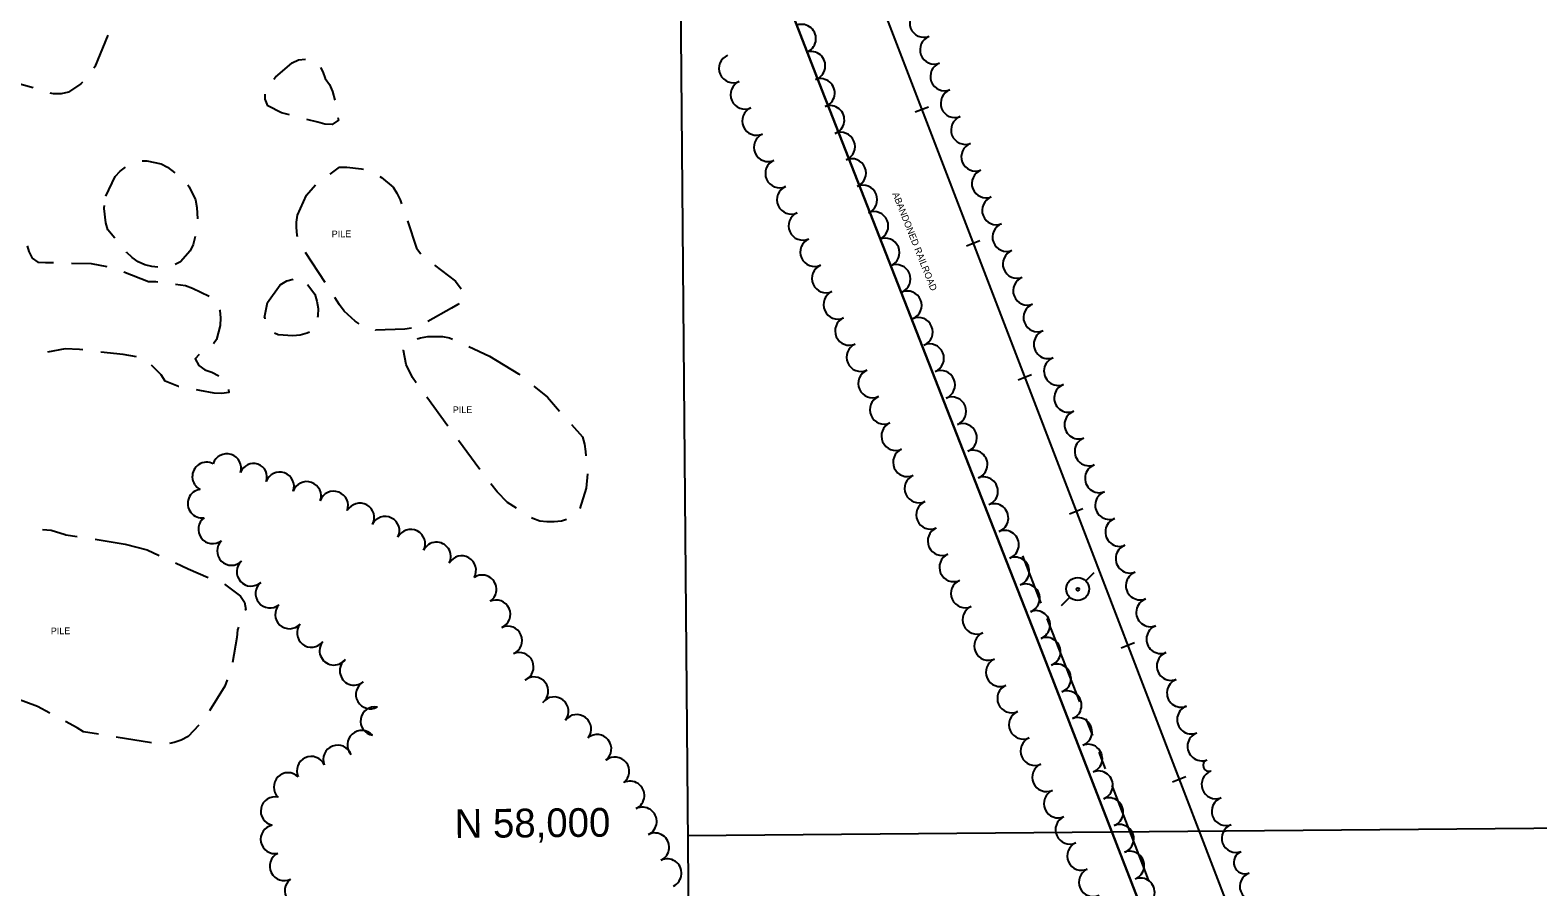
# Model space of a CAD drawing. Extents: x -2233 to 187241, y 4582 to 150524.
# Drawn here: x 104550 to 105601, y 57965 to 58561 of the extents above; entities that cross this region are included whole.
import ezdxf

# ---------------------------------------------------------------- set-up
doc = ezdxf.new("R2010")
doc.units = 0
for name, color, linetype in [('BLDG', 7, 'Continuous'), ('DIVISIONS', 7, 'Continuous'), ('DV_X_Corp_Line', 7, 'Continuous'), ('GRID', 7, 'Continuous'), ('RR', 7, 'Continuous'), ('TI_BORDER', 7, 'Continuous'), ('TRANSPWRLN', 7, 'Continuous'), ('TREES', 7, 'Continuous')]:
    doc.layers.add(name, color=color, linetype=linetype)

msp = doc.modelspace()

# ---------------------------------------------------------------- linework, layer by layer
at = {"layer": 'BLDG'}
for p, q in [((104720.3, 58527.3), (104721.4, 58528.6)), ((104756, 58385.6), (104742.3, 58406.5)), ((104856.1, 58341), (104870.5, 58334.3)), ((104841.6, 58285.6), (104826.8, 58305.8)), ((104863.7, 58255.3), (104849, 58275.5)), ((104595.6, 58206.7), (104616.6, 58203.3)), ((104635, 58064.9), (104610.3, 58068.9))]:
    msp.add_line(p, q, dxfattribs=at)
for points in [[(104604.6, 58558), (104595.4, 58536), (104594.7, 58535)], [(104721.4, 58528.6), (104732.9, 58538.6), (104737.5, 58540.7), (104742.2, 58541.2)], [(104752.7, 58535.4), (104754.3, 58532.4), (104756.1, 58527.7), (104759, 58523.5), (104761.1, 58518.8), (104762.8, 58512.7)], [(104552.4, 58521.2), (104536.5, 58525.8), (104531.2, 58525.4), (104528.1, 58525.1)], [(104586.9, 58525.3), (104585.6, 58524), (104577.1, 58518.3), (104572, 58517.1), (104566.6, 58517.1), (104564.4, 58517.6)], [(104731.2, 58502.4), (104725.5, 58503.8), (104716.1, 58508.7), (104714.2, 58513.3), (104714.1, 58516.9)], [(104764.9, 58500.5), (104765.2, 58498.7), (104761, 58495.8), (104755.8, 58496), (104750.9, 58497.3), (104743.3, 58499.3)], [(104628.4, 58470.5), (104631.8, 58470.5), (104641.7, 58468.4), (104646.2, 58465.9), (104651.2, 58462)], [(104603.1, 58445.8), (104609.7, 58459.4), (104613.2, 58463.1), (104616.9, 58466.1)], [(104759.4, 58461.2), (104766.1, 58466.1), (104771.2, 58465.9), (104781.4, 58464.9), (104782.7, 58464.5)], [(104794.1, 58459.6), (104795.3, 58458.9), (104803.3, 58452.1), (104806, 58447.9), (104808.3, 58443.3), (104809.3, 58440.5)], [(104660.3, 58453.6), (104661.3, 58452.3), (104665.6, 58443.2), (104666.5, 58437.9), (104667.1, 58430)], [(104736.7, 58432.5), (104742.9, 58446.6), (104749.3, 58453.8)], [(104609.4, 58416.5), (104604.5, 58422.3), (104603.1, 58427.3), (104601.9, 58437.2), (104602, 58437.7), (104602.2, 58439.4)], [(104736.8, 58417.5), (104736.5, 58418.7), (104736, 58423.9), (104736.1, 58427.6), (104736.7, 58432.5)], [(104813.3, 58428.6), (104819.7, 58409.5), (104822.7, 58405.7)], [(104665.5, 58417.7), (104664, 58412.2), (104661.8, 58407.6), (104655.1, 58400.1), (104651.4, 58398.2)], [(104548.3, 58411.1), (104549.4, 58407.3), (104551.7, 58402.6), (104555.8, 58399.7), (104561, 58399.6), (104566.6, 58399.5)], [(104639.3, 58396.3), (104635.3, 58396.8), (104630.3, 58397.9), (104625.7, 58400.1), (104621.6, 58403), (104617.8, 58406.5), (104617.5, 58406.9)], [(104579.1, 58399.2), (104592.8, 58398.9), (104603.9, 58396.9)], [(104832.2, 58397.6), (104846.8, 58386.6), (104850.7, 58381.2)], [(104615.7, 58393), (104632.8, 58386.3), (104638, 58386.3), (104639.4, 58386.1)], [(104651.8, 58384.5), (104658.7, 58383.6), (104663.5, 58381.7), (104675.1, 58376.2)], [(104715.8, 58371.7), (104724.7, 58383.9), (104729.2, 58386.8), (104733.6, 58388)], [(104743.7, 58384.3), (104748.7, 58377.6), (104750.3, 58372.6), (104751.1, 58367.5), (104751, 58362.4), (104750.7, 58361.3)], [(104779.6, 58356.8), (104776.9, 58358.7), (104769.3, 58365.7), (104766.1, 58370), (104762.8, 58375.1)], [(104682.3, 58366.7), (104682.5, 58366.1), (104683.1, 58361), (104682.9, 58355.6), (104680.3, 58345.9), (104678.2, 58342.8)], [(104714.1, 58360.4), (104714.1, 58360.6), (104713.8, 58361.2), (104715.8, 58371.7)], [(104849.3, 58370.9), (104848.5, 58370.2), (104844.1, 58367.7), (104827.5, 58358.5)], [(104816.1, 58353.8), (104811.6, 58353.2), (104791.1, 58352.5), (104791.1, 58352.5)], [(104745, 58351.1), (104743.5, 58350.3), (104738.6, 58348.9), (104733.5, 58348.4), (104723.2, 58349.1), (104720.7, 58350.3)], [(104820.2, 58346.5), (104822.5, 58347.2), (104827.5, 58347.9), (104837.7, 58347.9), (104842.7, 58347.1), (104844.8, 58346.2)], [(104587.2, 58338.7), (104584.8, 58339), (104574.7, 58339.5), (104562.5, 58337)], [(104624.4, 58333.8), (104615.3, 58335.4), (104599.7, 58337.2)], [(104668.2, 58335.4), (104665.5, 58332.4), (104668, 58327.9), (104672.2, 58324.9), (104676.9, 58323.1), (104681.8, 58320.6)], [(104819.5, 58315.8), (104816.9, 58319.4), (104812.4, 58328.6), (104810.6, 58338.3), (104810.9, 58338.7)], [(104870.5, 58334.3), (104890.8, 58322), (104891.7, 58321.2)], [(104654.1, 58313.1), (104653.7, 58313.1), (104644.5, 58317), (104641.8, 58321.2), (104635, 58328)], [(104688.6, 58311.2), (104688.9, 58309.1), (104683.9, 58308.4), (104678.7, 58308.5), (104668.6, 58310.3), (104666.4, 58310.9)], [(104901.5, 58313.3), (104910.9, 58305.7), (104919.4, 58296.1)], [(104927.8, 58286.7), (104935.4, 58278.2), (104936.7, 58273.1), (104937.4, 58268), (104937.7, 58264.9)], [(104938.9, 58252.4), (104937.9, 58242.3), (104933.5, 58228.1)], [(104889.3, 58228.3), (104883.2, 58232.3), (104876, 58239.7), (104871.4, 58245.4)], [(104924.3, 58220.4), (104920.8, 58219.4), (104915.7, 58218.8), (104910.6, 58218.8), (104905.6, 58219.4), (104900.8, 58221.3), (104899.9, 58221.7)], [(104558.9, 58213.5), (104565.1, 58213.1), (104574.9, 58210.1), (104575.2, 58209.9), (104583.2, 58208.6)], [(104616.6, 58203.3), (104631.9, 58199.3), (104640.2, 58195.5)], [(104651.6, 58190.3), (104660.6, 58186.2), (104674.4, 58180)], [(104685.8, 58175.5), (104697, 58167.1), (104699.7, 58162.9), (104700.6, 58157.8), (104700.3, 58157)], [(104695.6, 58145.5), (104695, 58143.6), (104694.4, 58138.3), (104691.4, 58120.9)], [(104687.7, 58108.9), (104686.1, 58104.4), (104675.3, 58087.3)], [(104564, 58085.6), (104555.6, 58090.1), (104541.1, 58095.6)], [(104598, 58070.9), (104587.5, 58072.6), (104583.2, 58075.4), (104575, 58079.8)], [(104667.9, 58077.3), (104660.5, 58069.3), (104655.6, 58066.8), (104650.8, 58065.2), (104647.4, 58064.4)]]:
    msp.add_lwpolyline(points, dxfattribs=at)
at = {"layer": 'DIVISIONS'}
for p, q in [((105255.1, 58162.2), (105242.2, 58195.3)), ((105291, 58070.1), (105286.4, 58081.7)), ((105300, 58046.8), (105295.5, 58058.4)), ((105330.2, 57968.7), (105327.1, 57976.8))]:
    msp.add_line(p, q, dxfattribs=at)
for points in [[(105281.9, 58093.4), (105260.4, 58148.5), (105259.2, 58151.6)], [(105327.1, 57976.8), (105304.9, 58034.1), (105304.5, 58035.1)]]:
    msp.add_lwpolyline(points, dxfattribs=at)
at = {"layer": 'DV_X_Corp_Line'}
for p, q in [((105103.8, 58515.7), (104983.8, 58824.7)), ((105103.8, 58515.7), (104983.8, 58824.7)), ((104983.8, 58824.7), (105103.8, 58515.7)), ((104983.8, 58824.7), (105103.8, 58515.7)), ((105105.6, 58511.1), (105103.8, 58515.7)), ((105105.6, 58511.1), (105103.8, 58515.7)), ((105103.8, 58515.7), (105105.6, 58511.1)), ((105103.8, 58515.7), (105105.6, 58511.1)), ((105230.6, 58192), (105105.6, 58511.1)), ((105230.6, 58192), (105105.6, 58511.1)), ((105105.6, 58511.1), (105230.6, 58192)), ((105105.6, 58511.1), (105230.6, 58192)), ((105238.8, 58171.3), (105230.6, 58192)), ((105238.8, 58171.3), (105230.6, 58192)), ((105230.6, 58192), (105238.8, 58171.3)), ((105230.6, 58192), (105238.8, 58171.3)), ((105253.6, 58133.5), (105238.8, 58171.3)), ((105253.6, 58133.5), (105238.8, 58171.3)), ((105238.8, 58171.3), (105253.6, 58133.5)), ((105238.8, 58171.3), (105253.6, 58133.5)), ((105409.5, 57731.9), (105253.6, 58133.5)), ((105409.5, 57731.9), (105253.6, 58133.5)), ((105253.6, 58133.5), (105409.5, 57731.9)), ((105253.6, 58133.5), (105409.5, 57731.9))]:
    msp.add_line(p, q, dxfattribs=at)
at = {"layer": 'GRID'}
for p, q in [((104991.3, 60000), (105014.8, 57302.3)), ((110008.5, 58043.7), (105008.7, 58000))]:
    msp.add_line(p, q, dxfattribs=at)
at = {"layer": 'RR'}
for p, q in [((105167.2, 58504.5), (105176.5, 58508.1)), ((105203, 58411.2), (105212.4, 58414.8)), ((105238.9, 58317.9), (105248.3, 58321.5)), ((105274.8, 58224.5), (105284.1, 58228.1)), ((105310.7, 58131.2), (105320, 58134.8)), ((105346.5, 58037.8), (105355.9, 58041.4))]:
    msp.add_line(p, q, dxfattribs=at)
msp.add_lwpolyline([(105007.1, 58925.1), (105096.6, 58702), (105289.2, 58201.1), (105384.5, 57953), (105435.1, 57829.4)], dxfattribs=at)
at = {"layer": 'TI_BORDER'}
msp.add_line((104999.5, 59062.3), (105026.2, 56000.1), dxfattribs=at)
at = {"layer": 'TRANSPWRLN'}
for p, q in [((105286.1, 58177.7), (105291.9, 58183.5)), ((105269.3, 58160.5), (105275, 58166.4))]:
    msp.add_line(p, q, dxfattribs=at)
for centre, radius in [((105280.5, 58172.1), 8.01), ((105280.5, 58171.9), 1)]:
    msp.add_circle(centre, radius, dxfattribs=at)
at = {"layer": 'TREES'}
for centre, radius, start, end in [((105173.4, 58566.5), 10, 111.1323, 291.1323), ((105088.1, 58555.5), 10, 289.1036, 109.1036), ((105180.6, 58547.8), 10, 111.1323, 291.1323), ((105040.5, 58534.8), 10, 113.8433, 293.8433), ((105094.6, 58536.6), 10, 289.1036, 109.1036), ((105187.8, 58529.2), 10, 111.1323, 291.1323), ((105048.6, 58516.5), 10, 113.8433, 293.8433), ((105101.2, 58517.7), 10, 289.1036, 109.1036), ((105195, 58510.5), 10, 111.1323, 291.1323), ((105056.7, 58498.2), 10, 113.8433, 293.8433), ((105107.9, 58498.9), 10, 290.4541, 110.4541), ((105202.2, 58491.9), 10, 111.1323, 291.1323), ((105115.3, 58480.3), 10, 292.7898, 112.7898), ((105064.8, 58479.9), 10, 113.8433, 293.8433), ((105209.4, 58473.2), 10, 111.1323, 291.1323), ((105072.8, 58461.6), 10, 113.8433, 293.8433), ((105123, 58461.9), 10, 292.7898, 112.7898), ((105216.7, 58454.6), 10, 111.1323, 291.1323), ((105080.9, 58443.3), 10, 113.8433, 293.8433), ((105130.8, 58443.4), 10, 292.7898, 112.7898), ((105223.9, 58435.9), 10, 111.1323, 291.1323), ((105089, 58425.1), 10, 113.8433, 293.8433), ((105138.5, 58425), 10, 292.7898, 112.7898), ((105231.1, 58417.3), 10, 111.1323, 291.1323), ((105146.3, 58406.5), 10, 292.7898, 112.7898), ((105097.1, 58406.8), 10, 113.8433, 293.8433), ((105238.3, 58398.6), 10, 111.1323, 291.1323), ((105105.2, 58388.5), 10, 113.8433, 293.8433), ((105154, 58388.1), 10, 292.7898, 112.7898), ((105245.5, 58379.9), 10, 111.1323, 291.1323), ((105113.3, 58370.2), 10, 113.8433, 293.8433), ((105161.8, 58369.7), 10, 292.7898, 112.7898), ((105252.7, 58361.3), 10, 111.0484, 291.0484), ((105121.4, 58351.9), 10, 113.8433, 293.8433), ((105169.5, 58351.2), 10, 292.7898, 112.7898), ((105129.4, 58333.6), 10, 113.8433, 293.8433), ((105177.3, 58332.8), 10, 292.7898, 112.7898), ((105259.9, 58342.6), 10, 110.922, 290.922), ((105267, 58323.9), 10, 110.922, 290.922), ((105137.5, 58315.3), 10, 113.8433, 293.8433), ((105185, 58314.3), 10, 292.7898, 112.7898), ((105274.1, 58305.2), 10, 110.922, 290.922), ((105145.6, 58297), 10, 113.8433, 293.8433), ((105192.8, 58295.9), 10, 292.7898, 112.7898), ((105281.3, 58286.6), 10, 110.922, 290.922), ((105153.7, 58278.7), 10, 113.8433, 293.8433), ((105200.3, 58277.4), 10, 291.627, 111.627), ((105161.8, 58260.4), 10, 113.8433, 293.8433), ((105288.4, 58267.9), 10, 110.922, 290.922), ((104673.4, 58250.4), 10, 62.6964, 242.6964), ((104687.5, 58256.3), 10, 342.6275, 162.6275), ((104706, 58250.1), 9.47, 340.4837, 160.4837), ((105207.6, 58258.8), 10, 291.3511, 111.3511), ((105295.6, 58249.2), 10, 110.922, 290.922), ((104724.3, 58243.6), 10, 340.4837, 160.4837), ((105169.9, 58242.1), 10, 113.8433, 293.8433), ((105214.9, 58240.2), 10, 291.3511, 111.3511), ((104670.2, 58231.6), 10, 98.1496, 278.1496), ((104743.2, 58236.9), 10, 340.4837, 160.4837), ((104762, 58230.2), 10, 339.9893, 159.9893), ((105302.7, 58230.5), 10, 110.922, 290.922), ((104780.2, 58221.9), 10, 331.0293, 151.0293), ((105177.9, 58223.8), 10, 113.8433, 293.8433), ((105222.2, 58221.5), 10, 291.3511, 111.3511), ((104677.6, 58213.7), 10, 126.9029, 306.9029), ((104797.8, 58212.6), 10, 333.3463, 153.3463), ((105309.8, 58211.8), 10, 110.922, 290.922), ((104815.7, 58203.6), 10, 333.3464, 153.3464), ((105186, 58205.5), 10, 113.8433, 293.8433), ((105229.5, 58202.9), 10, 291.3511, 111.3511), ((104690.7, 58198.6), 10, 134.9171, 314.9171), ((104833.6, 58194.7), 10, 333.4765, 153.4765), ((105194.1, 58187.2), 10, 113.8433, 293.8433), ((105317, 58193.2), 10, 110.922, 290.922), ((104704.4, 58184.1), 10, 131.8936, 311.8936), ((104851.2, 58185.2), 10, 329.8613, 149.8613), ((105236.8, 58184.3), 10, 291.3511, 111.3511), ((104717.4, 58168.9), 10, 129.2903, 309.2903), ((104865.4, 58171.8), 10, 303.8258, 123.8258), ((105202.2, 58169), 10, 113.8433, 293.8433), ((105244.1, 58165.6), 10, 291.3511, 111.3511), ((105324.1, 58174.5), 10, 110.922, 290.922), ((104875.1, 58154.4), 10, 294.5092, 114.5092), ((105331.3, 58155.8), 10, 110.922, 290.922), ((104731.2, 58154.4), 10, 137.7856, 317.7856), ((105210.3, 58150.7), 10, 113.8433, 293.8433), ((105251.3, 58147), 10, 291.3511, 111.3511), ((104746.4, 58141.5), 10, 141.7707, 321.7707), ((104883.3, 58136.2), 9.99, 293.5466, 113.5466), ((105338.4, 58137.1), 10, 110.922, 290.922), ((104762.1, 58129.1), 10, 141.4612, 321.4612), ((105218.4, 58132.4), 10, 113.8433, 293.8433), ((105258.6, 58128.4), 10, 291.3511, 111.3511), ((104776.2, 58115.1), 10, 128.8592, 308.8592), ((104891.3, 58117.8), 10, 293.5466, 113.5466), ((105226.5, 58114.1), 10, 113.8433, 293.8433), ((105345.6, 58118.4), 10, 110.922, 290.922), ((105265.9, 58109.8), 10, 291.3511, 111.3511), ((104787.4, 58098.6), 10, 119.4603, 299.4603), ((104901.5, 58100.8), 10, 308.3241, 128.3241), ((105234.5, 58095.8), 10, 113.8433, 293.8433), ((105273.2, 58091.1), 10, 291.3511, 111.3511), ((105352.7, 58099.7), 10, 110.922, 290.922), ((104915.6, 58086.9), 10, 322.2469, 142.2469), ((105359.8, 58081.1), 10, 110.922, 290.922), ((104790.7, 58080), 10, 80.4069, 260.4069), ((104931.4, 58074.6), 10, 322.3985, 142.3985), ((105242.6, 58077.5), 10, 113.8433, 293.8433), ((105280.5, 58072.5), 10, 291.3511, 111.3511), ((104781.5, 58063.5), 10, 41.5464, 221.5464), ((104945.5, 58060.7), 10, 308.4211, 128.4211), ((105367, 58062.4), 10, 110.922, 290.922), ((104764.7, 58053.3), 10, 21.3869, 201.3869), ((105250.7, 58059.2), 10, 113.8433, 293.8433), ((105287.7, 58053.9), 10, 291.3511, 111.3511), ((104746.3, 58045.4), 10, 24.7157, 204.7157), ((104958, 58045), 10, 308.418, 128.418), ((105258.8, 58040.9), 10, 113.8433, 293.8433), ((105372, 58049.2), 4.14, 110.472, 290.472), ((104730.2, 58034.1), 10, 45.3244, 225.3244), ((104968.5, 58028.2), 10, 295.6137, 115.6137), ((105295, 58035.3), 10, 291.3511, 111.3511), ((105376.9, 58035.9), 10, 110.472, 290.472), ((104721.1, 58017.3), 10, 78.105, 258.105), ((105266.9, 58022.6), 10, 113.9334, 293.9334), ((104977.1, 58010.1), 10, 295.6137, 115.6137), ((105302.3, 58016.6), 10, 291.3511, 111.3511), ((105383.9, 58017.2), 10, 110.472, 290.472), ((104721, 57997.7), 10, 101.0934, 281.0934), ((105275, 58004.3), 10, 114.0698, 294.0698), ((105309.6, 57998), 10, 291.3511, 111.3511), ((105390.9, 57998.5), 10, 110.472, 290.472), ((104985.8, 57992.1), 10, 295.6137, 115.6137), ((104727.4, 57978.9), 10, 116.438, 296.438), ((105283.2, 57986.1), 10, 114.0698, 294.0698), ((105316.9, 57979.4), 10, 291.3511, 111.3511), ((105397.2, 57981.6), 7.95, 110.472, 290.472), ((104994.4, 57974.1), 10, 295.6137, 115.6137), ((105291.3, 57967.8), 10, 114.0698, 294.0698), ((104737.9, 57962), 10, 127.6327, 307.6327), ((105324.2, 57960.7), 10, 291.3511, 111.3511), ((105403.5, 57964.8), 10, 110.472, 290.472)]:
    msp.add_arc(centre, radius, start, end, dxfattribs=at)

# ---------------------------------------------------------------- texts
at = {"layer": 'BLDG'}
for p in [(104760.6, 58417.1), (104845, 58294.6), (104564.8, 58140.5)]:
    msp.add_text('PILE', height=4.68, rotation=0.5, dxfattribs=at).set_placement(p)
at = {"layer": 'GRID'}
msp.add_text('N 58,000', height=20, rotation=0.5, dxfattribs=at).set_placement((104846.3, 57998.6))
at = {"layer": 'RR'}
msp.add_text('ABANDONED RAILROAD', height=4.68, rotation=291.704, dxfattribs=at).set_placement((105151.2, 58447.5))

doc.saveas('drawing.dxf')
